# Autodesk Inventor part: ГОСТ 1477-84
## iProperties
Created: 2009-12
Part Number: ГОСТ 1477-84
Document SubType Name: Modeling
Designer: Роман
Density: 1 g/cm^3
Mass: 0.679155 g
Surface Area: 5.21885 cm^2
Volume: 0.679155 cm^3
Author: Роман
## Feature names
1. Revolution1
2. Extrusion1
3. Chamfer1
4. Chamfer2
